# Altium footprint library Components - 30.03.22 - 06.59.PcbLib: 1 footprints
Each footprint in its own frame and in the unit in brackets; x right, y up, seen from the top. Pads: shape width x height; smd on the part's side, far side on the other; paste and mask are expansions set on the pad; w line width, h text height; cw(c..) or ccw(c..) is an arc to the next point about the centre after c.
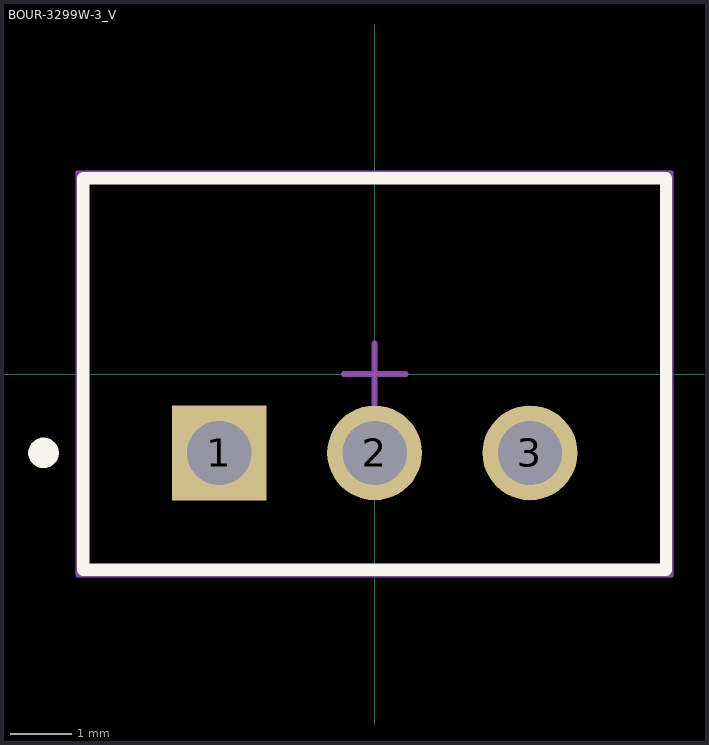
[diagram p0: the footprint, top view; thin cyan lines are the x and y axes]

## BOUR-3299W-3_V [mm] "TH, 3-Leads, Body 9.53x6.4mm, Pitch 2.54mm"
height 11.55
pads (3):
  rect 1.55x1.55 hole 1.05: 1(-2.54,-1.29)
  round 1.55 hole 1.05: 2(0,-1.29) 3(2.54,-1.29)
Top Overlay:
  circle w0.25: c-5.415,-1.29 r0.125
  lines w0.2: -4.765,-3.2 4.765,-3.2 4.765,3.2 -4.765,3.2 -4.765,-3.2
Mechanical 13:
  lines w0.1: -4.765,-3.2 -4.765,3.2 4.765,3.2 4.765,-3.2 -4.765,-3.2
Mechanical 15:
  lines w0.05: -4.865,-3.3 4.865,-3.3 4.865,3.3 -4.865,3.3 -4.865,-3.3
  lines w0.1: -0.5,0 0.5,0 ; 0,-0.5 0,0.5
3D body: height 11.55, standoff 10.03, extent -4.765,0.91 -2.476,3.2
3D body: height 10.03, standoff 0.38, extent -4.765,-3.2 4.765,3.2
